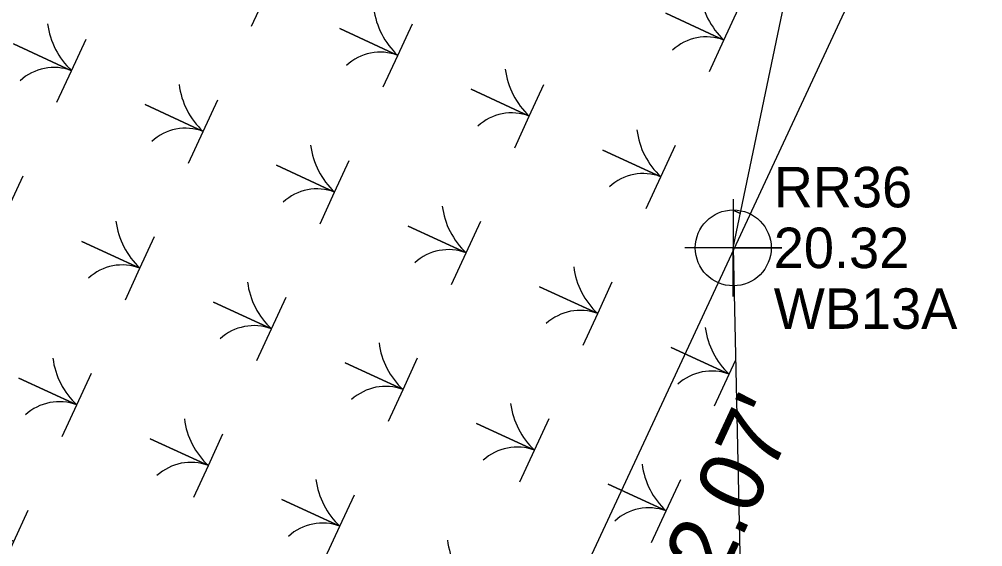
# Model space of a CAD drawing. Extents: x 2532037 to 2533565, y 713396 to 716867.
# Drawn here: x 2532822.3 to 2532881.8, y 715682.5 to 715715.1 of the extents above; entities that cross this region are included whole.
import ezdxf

# ---------------------------------------------------------------- set-up
doc = ezdxf.new("R2010")
doc.units = 0
for name, color, linetype in [('Exist Environmental Wetland Boundary', 7, 'Continuous'), ('Exist Environmental Wetland Boundary Cogo Comment', 7, 'Continuous'), ('Exist Environmental Wetland Boundary Cogo Elevation', 7, 'Continuous'), ('Exist Environmental Wetland Boundary Cogo Number', 7, 'Continuous'), ('Exist Environmental Wetland Boundary Cogo Point CELL', 7, 'Continuous'), ('Exist Right of Way Line', 7, 'Continuous'), ('Exist Structure Major Bridge Seat Top Elevation', 7, 'Continuous'), ('Scratch_Level_1', 7, 'Continuous')]:
    doc.layers.add(name, color=color, linetype=linetype)

msp = doc.modelspace()

# ---------------------------------------------------------------- linework, layer by layer
at = {"layer": 'Exist Environmental Wetland Boundary'}
for q in [(2532875.119, 715742.999), (2532867.338, 715654.282)]:
    msp.add_line((2532866.358, 715700.97), q, dxfattribs=at)
at = {"layer": 'Exist Environmental Wetland Boundary Cogo Point CELL'}
msp.add_lwpolyline([(2532866.358, 715703.97), (2532866.358, 715697.97), (2532866.358, 715700.97), (2532869.358, 715700.97), (2532863.358, 715700.97)], dxfattribs=at)
msp.add_circle((2532866.358, 715700.97), 2.344, dxfattribs=at)
at = {"layer": 'Exist Right of Way Line'}
msp.add_line((2532693.616, 715329.517), (2532895.636, 715763.738), dxfattribs=at)
at = {"layer": 'Scratch_Level_1'}
for points in [[(2532836.619, 715714.655), (2532837.52, 715716.607), (2532833.939, 715718.261), (2532837.52, 715716.607), (2532838.422, 715718.559)], [(2532864.882, 715711.851), (2532865.783, 715713.803), (2532862.201, 715715.457), (2532865.783, 715713.803), (2532866.685, 715715.756)], [(2532844.741, 715710.905), (2532845.642, 715712.858), (2532842.06, 715714.511), (2532845.642, 715712.858), (2532846.543, 715714.81)], [(2532824.599, 715709.96), (2532825.501, 715711.912), (2532821.919, 715713.566), (2532825.501, 715711.912), (2532826.402, 715713.864)], [(2532852.862, 715707.156), (2532853.763, 715709.108), (2532850.181, 715710.762), (2532853.763, 715709.108), (2532854.665, 715711.061)], [(2532832.721, 715706.21), (2532833.622, 715708.163), (2532830.04, 715709.816), (2532833.622, 715708.163), (2532834.523, 715710.115)], [(2532860.983, 715703.407), (2532861.885, 715705.359), (2532858.303, 715707.013), (2532861.885, 715705.359), (2532862.786, 715707.311)], [(2532840.842, 715702.461), (2532841.743, 715704.413), (2532838.162, 715706.067), (2532841.743, 715704.413), (2532842.645, 715706.366)], [(2532820.701, 715701.515), (2532821.602, 715703.468), (2532818.02, 715705.121), (2532821.602, 715703.468), (2532822.503, 715705.42)], [(2532866.8, 715703.09), (2532866.424, 715703.263), (2532866.8, 715703.09)], [(2532848.964, 715698.712), (2532849.865, 715700.664), (2532846.283, 715702.318), (2532849.865, 715700.664), (2532850.766, 715702.616)], [(2532828.822, 715697.766), (2532829.724, 715699.718), (2532826.142, 715701.372), (2532829.724, 715699.718), (2532830.625, 715701.671)], [(2532857.085, 715694.962), (2532857.986, 715696.915), (2532854.404, 715698.568), (2532857.986, 715696.915), (2532858.888, 715698.867)], [(2532836.944, 715694.017), (2532837.845, 715695.969), (2532834.263, 715697.623), (2532837.845, 715695.969), (2532838.746, 715697.921)], [(2532865.206, 715691.213), (2532866.108, 715693.165), (2532862.526, 715694.819), (2532866.108, 715693.165), (2532866.504, 715694.023)], [(2532845.065, 715690.267), (2532845.966, 715692.22), (2532842.385, 715693.873), (2532845.966, 715692.22), (2532846.868, 715694.172)], [(2532824.924, 715689.322), (2532825.825, 715691.274), (2532822.243, 715692.928), (2532825.825, 715691.274), (2532826.726, 715693.226)], [(2532853.187, 715686.518), (2532854.088, 715688.47), (2532850.506, 715690.124), (2532854.088, 715688.47), (2532854.989, 715690.423)], [(2532833.045, 715685.572), (2532833.947, 715687.525), (2532830.365, 715689.178), (2532833.947, 715687.525), (2532834.848, 715689.477)], [(2532861.308, 715682.768), (2532862.209, 715684.721), (2532858.627, 715686.374), (2532862.209, 715684.721), (2532863.111, 715686.673)], [(2532841.167, 715681.823), (2532842.068, 715683.775), (2532838.486, 715685.429), (2532842.068, 715683.775), (2532842.969, 715685.728)], [(2532821.025, 715680.877), (2532821.927, 715682.83), (2532818.345, 715684.483), (2532821.927, 715682.83), (2532822.828, 715684.782)]]:
    msp.add_lwpolyline(points, dxfattribs=at)
for centre, radius, start, end in [((2532869.07, 715717.309), 4.806, 187.34643, 226.84116), ((2532848.929, 715716.363), 4.806, 187.34643, 226.84116), ((2532828.788, 715715.418), 4.806, 187.34643, 226.84116), ((2532864.699, 715710.926), 3.075, 69.35932, 132.75394), ((2532844.558, 715709.98), 3.075, 69.35932, 132.75394), ((2532824.417, 715709.035), 3.075, 69.35932, 132.75394), ((2532857.05, 715712.614), 4.806, 187.34643, 226.84116), ((2532836.909, 715711.668), 4.806, 187.34643, 226.84116), ((2532852.679, 715706.231), 3.075, 69.35932, 132.75394), ((2532832.538, 715705.285), 3.075, 69.35932, 132.75394), ((2532865.172, 715708.864), 4.806, 187.34643, 226.84116), ((2532845.031, 715707.919), 4.806, 187.34643, 226.84116), ((2532860.801, 715702.482), 3.075, 69.35932, 132.75394), ((2532840.66, 715701.536), 3.075, 69.35932, 132.75394), ((2532853.152, 715704.169), 4.806, 187.34643, 226.84116), ((2532833.011, 715703.224), 4.806, 187.34643, 226.84116), ((2532848.781, 715697.787), 3.075, 69.35932, 132.75394), ((2532828.64, 715696.841), 3.075, 69.35932, 132.75394), ((2532861.273, 715700.42), 4.806, 187.34643, 226.84116), ((2532841.132, 715699.474), 4.806, 187.34643, 226.84116), ((2532856.902, 715694.037), 3.075, 69.35932, 132.75394), ((2532836.761, 715693.092), 3.075, 69.35932, 132.75394), ((2532869.395, 715696.671), 4.806, 187.34643, 226.84116), ((2532849.254, 715695.725), 4.806, 187.34643, 226.84116), ((2532829.112, 715694.779), 4.806, 187.34643, 226.84116), ((2532865.024, 715690.288), 3.075, 69.35932, 132.75394), ((2532844.883, 715689.342), 3.075, 69.35932, 132.75394), ((2532824.741, 715688.397), 3.075, 69.35932, 132.75394), ((2532857.375, 715691.976), 4.806, 187.34643, 226.84116), ((2532837.234, 715691.03), 4.806, 187.34643, 226.84116), ((2532853.004, 715685.593), 3.075, 69.35932, 132.75394), ((2532832.863, 715684.647), 3.075, 69.35932, 132.75394), ((2532865.496, 715688.226), 4.806, 187.34643, 226.84116), ((2532845.355, 715687.281), 4.806, 187.34643, 226.84116), ((2532861.125, 715681.844), 3.075, 69.35932, 132.75394), ((2532840.984, 715680.898), 3.075, 69.35932, 132.75394), ((2532853.477, 715683.531), 4.806, 187.34643, 226.84116)]:
    msp.add_arc(centre, radius, start, end, dxfattribs=at)

# ---------------------------------------------------------------- texts
at = {"layer": 'Exist Environmental Wetland Boundary Cogo Comment'}
msp.add_text('WB13A', height=2.5, dxfattribs=at).set_placement((2532868.858, 715695.97))
at = {"layer": 'Exist Environmental Wetland Boundary Cogo Elevation'}
msp.add_text('20.32', height=2.5, dxfattribs=at).set_placement((2532868.858, 715699.72))
at = {"layer": 'Exist Environmental Wetland Boundary Cogo Number'}
msp.add_text('RR36', height=2.5, dxfattribs=at).set_placement((2532868.858, 715703.47))
at = {"layer": 'Exist Structure Major Bridge Seat Top Elevation'}
msp.add_text("BS3=22.07'", height=4, rotation=65.05, dxfattribs=at).set_placement((2532858.753, 715665.558))

doc.saveas('drawing.dxf')
